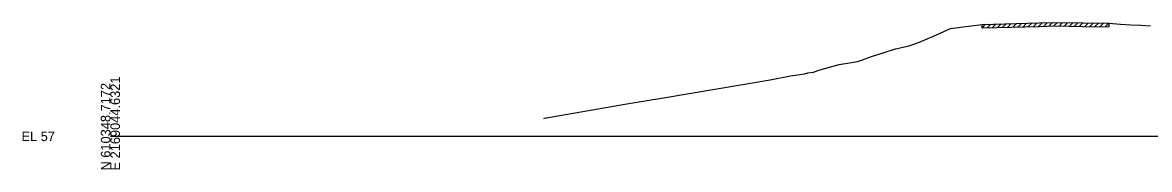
# Model space of a CAD drawing. Extents: x -26 to 6803, y -10 to 19606.
# Drawn here: x 1974.3 to 2303.8, y 11490.3 to 11533.3 of the extents above; entities that cross this region are included whole.
import ezdxf

# ---------------------------------------------------------------- set-up
doc = ezdxf.new("R2010")
doc.units = 0
for name, color, linetype in [('RD_GPK_XS_Cell', 7, 'Continuous'), ('RD_XS_ExGround', 7, 'Continuous'), ('RD_XS_ExPaveRet', 7, 'Continuous')]:
    doc.layers.add(name, color=color, linetype=linetype)

msp = doc.modelspace()

# ---------------------------------------------------------------- linework, layer by layer
at = {"layer": 'RD_GPK_XS_Cell'}
msp.add_line((2000, 11500), (2400, 11500), dxfattribs=at)
at = {"layer": 'RD_XS_ExGround'}
msp.add_lwpolyline([(2126.74, 11505.2), (2126.87, 11505.33), (2150.96, 11509.48), (2161.72, 11511.26), (2192.88, 11516.47), (2198.82, 11517.71), (2202.93, 11518.24), (2203.89, 11518.57), (2205.55, 11518.72), (2207.11, 11519.36), (2213.05, 11521.01), (2216.12, 11521.44), (2218.45, 11521.87), (2219.91, 11522.4), (2222.47, 11523.35), (2226.52, 11524.61), (2229.52, 11525.6), (2233.56, 11526.49), (2236.28, 11527.45), (2238.82, 11528.45), (2240.66, 11529.26), (2245.65, 11531.52), (2249.32, 11532.01), (2251.69, 11532.25), (2254.86, 11532.72), (2271.57, 11533.14), (2276.03, 11533.26), (2284.29, 11533.14), (2291.87, 11533.04), (2295.32, 11532.83), (2298.37, 11532.61), (2301.24, 11532.47), (2304.1, 11532.28)], dxfattribs=at)
at = {"layer": 'RD_XS_ExPaveRet'}
for p, q in [((2254.86, 11531.72), (2255.88, 11532.74)), ((2254.86, 11531.72), (2254.86, 11532.72)), ((2254.86, 11531.72), (2271.57, 11532.14)), ((2254.86, 11531.72), (2254.86, 11531.72)), ((2256.36, 11531.75), (2257.38, 11532.78)), ((2257.86, 11531.79), (2258.88, 11532.82)), ((2259.36, 11531.83), (2260.38, 11532.86)), ((2260.86, 11531.87), (2261.88, 11532.89)), ((2262.36, 11531.9), (2263.38, 11532.93)), ((2263.86, 11531.94), (2264.88, 11532.97)), ((2265.36, 11531.98), (2266.38, 11533.01)), ((2266.86, 11532.02), (2267.88, 11533.04)), ((2268.36, 11532.06), (2269.38, 11533.08)), ((2269.86, 11532.09), (2270.88, 11533.12)), ((2271.36, 11532.13), (2272.39, 11533.16)), ((2271.57, 11532.14), (2276.03, 11532.26)), ((2272.86, 11532.17), (2273.89, 11533.2)), ((2274.36, 11532.21), (2275.39, 11533.24)), ((2275.86, 11532.25), (2276.85, 11533.25)), ((2276.03, 11532.26), (2284.29, 11532.14)), ((2277.36, 11532.24), (2278.34, 11533.23)), ((2278.86, 11532.22), (2279.84, 11533.21)), ((2280.36, 11532.2), (2281.34, 11533.18)), ((2281.86, 11532.18), (2282.84, 11533.16)), ((2283.36, 11532.16), (2284.34, 11533.14)), ((2284.29, 11532.14), (2291.87, 11532.04)), ((2284.86, 11532.14), (2285.84, 11533.12)), ((2286.36, 11532.11), (2287.34, 11533.1)), ((2287.86, 11532.09), (2288.84, 11533.08)), ((2289.36, 11532.07), (2290.34, 11533.06)), ((2290.86, 11532.05), (2291.84, 11533.04)), ((2291.87, 11533.04), (2291.87, 11532.04)), ((2291.87, 11532.04), (2291.87, 11532.04))]:
    msp.add_line(p, q, dxfattribs=at)

# ---------------------------------------------------------------- texts
at = {"layer": 'RD_GPK_XS_Cell'}
for s, p in [('N 610348.7172', (2000, 11490)), ('E 2169044.6321', (2002.8, 11490))]:
    msp.add_text(s, height=2.8, rotation=90, dxfattribs=at).set_placement(p)
msp.add_text('EL 57', height=2.8, dxfattribs=at).set_placement((1974, 11498.6))

doc.saveas('drawing.dxf')
